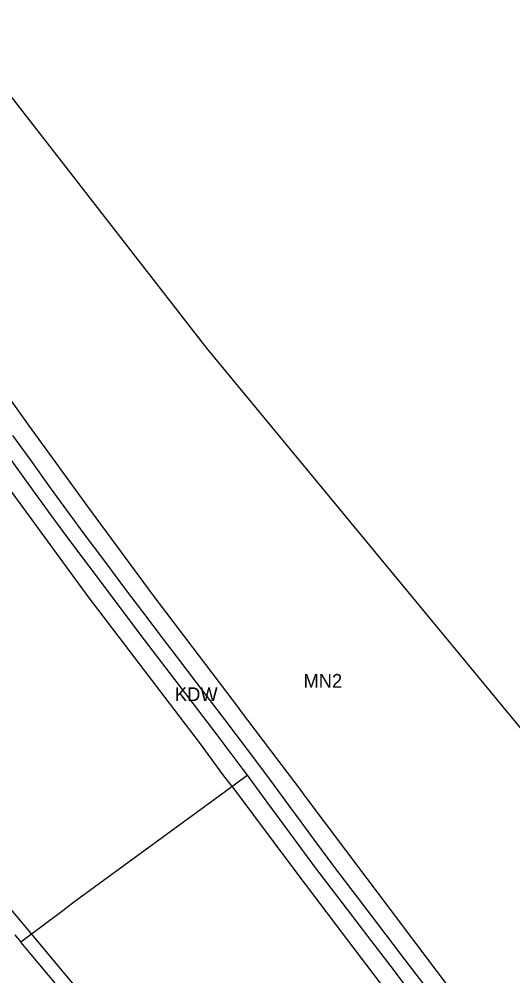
# Model space of a CAD drawing. Extents: x 7435758 to 7439981, y 5550649 to 5554049.
# Drawn here: x 7437444.8 to 7437632.3, y 5551959.4 to 5552322.5 of the extents above; entities that cross this region are included whole.
import ezdxf

# ---------------------------------------------------------------- set-up
doc = ezdxf.new("R2010")
doc.units = 0
for name, color, linetype in [('linie_rozgraniczające', 7, 'Continuous'), ('linie_zabudowy_nieprzekraczalne', 7, 'Continuous'), ('oznaczenia_przeznaczen', 7, 'Continuous')]:
    doc.layers.add(name, color=color, linetype=linetype)

msp = doc.modelspace()

# ---------------------------------------------------------------- linework, layer by layer
at = {"layer": 'linie_rozgraniczające'}
for p, q in [((7437516.1, 5552197.62), (7437418.98, 5552322.48)), ((7437577.43, 5552123.38), (7437516.1, 5552197.62)), ((7437448.98, 5552155.5), (7437442.45, 5552164.48)), ((7437436.07, 5552163.04), (7437447.53, 5552147.14)), ((7437456.77, 5552144.64), (7437448.98, 5552155.5)), ((7437447.53, 5552147.14), (7437456.84, 5552134.23)), ((7437464.33, 5552134.2), (7437456.77, 5552144.64)), ((7437456.84, 5552134.23), (7437463.18, 5552125.67)), ((7437469.54, 5552127.2), (7437464.33, 5552134.2)), ((7437477.04, 5552117.26), (7437469.54, 5552127.2)), ((7437463.18, 5552125.67), (7437471.29, 5552114.9)), ((7437712.83, 5551959.48), (7437577.43, 5552123.38)), ((7437485.41, 5552106.1), (7437477.04, 5552117.26)), ((7437471.29, 5552114.9), (7437480.87, 5552102.18)), ((7437491.86, 5552097.54), (7437485.41, 5552106.1)), ((7437480.87, 5552102.18), (7437490.64, 5552089.14)), ((7437499.63, 5552087.22), (7437491.86, 5552097.54)), ((7437490.64, 5552089.14), (7437500.52, 5552076.22)), ((7437506.29, 5552078.56), (7437499.63, 5552087.22)), ((7437500.52, 5552076.22), (7437510.48, 5552063.12)), ((7437514.63, 5552067.55), (7437506.29, 5552078.56)), ((7437522.95, 5552056.67), (7437514.63, 5552067.55)), ((7437510.48, 5552063.12), (7437520.24, 5552050.34)), ((7437531.55, 5552045.38), (7437522.95, 5552056.67)), ((7437520.24, 5552050.34), (7437529.75, 5552037.72)), ((7437538.83, 5552035.57), (7437531.55, 5552045.38)), ((7437529.75, 5552037.72), (7437531.36, 5552035.54)), ((7437526.54, 5552031.99), (7437531.36, 5552035.54)), ((7437531.36, 5552035.54), (7437538.85, 5552025.41)), ((7437547.22, 5552024.23), (7437538.83, 5552035.57)), ((7437465.45, 5551987.36), (7437526.53, 5552031.99)), ((7437526.53, 5552031.99), (7437526.54, 5552031.99)), ((7437538.85, 5552025.41), (7437547.91, 5552013.21)), ((7437551.91, 5552017.91), (7437547.22, 5552024.23)), ((7437556.73, 5552011.36), (7437551.91, 5552017.91)), ((7437547.91, 5552013.21), (7437557.39, 5552000.34)), ((7437565.08, 5552000.1), (7437556.73, 5552011.36)), ((7437557.39, 5552000.34), (7437567.31, 5551987.27)), ((7437573.33, 5551989.33), (7437565.08, 5552000.1)), ((7437581.47, 5551978.66), (7437573.33, 5551989.33)), ((7437461.37, 5551984.23), (7437465.45, 5551987.36)), ((7437567.31, 5551987.27), (7437577.08, 5551974.49)), ((7437445.45, 5551972.38), (7437461.37, 5551984.23)), ((7437589.82, 5551967.73), (7437581.47, 5551978.66)), ((7437445.45, 5551972.38), (7437443.31, 5551974.95)), ((7437577.08, 5551974.49), (7437587.18, 5551961.33)), ((7437445.64, 5551972.15), (7437445.45, 5551972.38)), ((7437448.82, 5551968.35), (7437445.64, 5551972.15)), ((7437487.61, 5551921.9), (7437448.82, 5551968.35)), ((7437600.85, 5551953.15), (7437589.82, 5551967.73)), ((7437587.18, 5551961.33), (7437596.99, 5551948.29))]:
    msp.add_line(p, q, dxfattribs=at)
at = {"layer": 'linie_zabudowy_nieprzekraczalne'}
for points in [[(7437622.67, 5551935.85), (7437603.54, 5551961.13), (7437576.99, 5551996.35), (7437552.66, 5552028.7), (7437552.66, 5552028.71), (7437528.54, 5552060.7), (7437528.53, 5552060.72), (7437495.79, 5552103.88), (7437470.94, 5552137.52), (7437448.78, 5552168.06), (7437423.25, 5552203.71)], [(7437605.29, 5551926.09), (7437569.67, 5551972.95), (7437569.66, 5551972.96), (7437549.64, 5551999.44), (7437549.63, 5551999.46), (7437526.05, 5552030.9), (7437526.04, 5552030.9), (7437525.79, 5552031.22), (7437522.21, 5552035.83), (7437513.69, 5552047.43), (7437471.05, 5552103.37), (7437470.99, 5552103.45), (7437442.61, 5552142.29), (7437442.61, 5552142.3), (7437442.58, 5552142.34), (7437416.92, 5552178.36), (7437404.27, 5552195.85)], [(7437320.93, 5552134.39), (7437324.87, 5552128.13), (7437325.53, 5552127.07), (7437338.6, 5552109.16), (7437366.58, 5552075.27), (7437366.59, 5552075.26), (7437415.01, 5552016.22), (7437445.57, 5551979.99), (7437450.09, 5551974.62), (7437491.45, 5551925.11)]]:
    msp.add_lwpolyline(points, dxfattribs=at)

# ---------------------------------------------------------------- texts
at = {"layer": 'oznaczenia_przeznaczen'}
for s, p in [('MN2', (7437552.81, 5552068.79)), ('KDW', (7437503.99, 5552063.7))]:
    msp.add_text(s, height=5.2, dxfattribs=at).set_placement(p)

doc.saveas('drawing.dxf')
